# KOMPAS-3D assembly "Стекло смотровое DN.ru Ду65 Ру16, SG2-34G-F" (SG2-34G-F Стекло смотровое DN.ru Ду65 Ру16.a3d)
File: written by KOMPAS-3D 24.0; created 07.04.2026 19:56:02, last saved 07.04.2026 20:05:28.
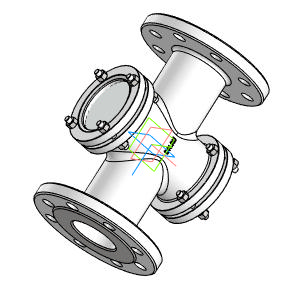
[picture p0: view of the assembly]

Document properties: Автор: Main; Полное имя файла: D:\DN.ru Аутсерс\Стекло смотровое DN.ru\Исходники\Стекло смотровое DN.ru SG2-34G-F тип В ГОСТ 21836-2021 Ду65 Ру16, углеродистая сталь, фланцевое\SG2-34G-F Стекло смотровое DN.ru Ду65 Ру16.a3d

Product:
- Component [detail]: Деталь  | qty 1  | pos. 1  | Масса: 12.292251; Автор: Main; additional columns: Типовые; source file: ДетальДеталь.m3d
- Component [detail]: Стекло  | qty 2  | pos. 2  | Масса: 0.331901; Автор: Main; source file: СтеклоСтекло.m3d
- Component [detail]: ANSI B18.2.4.2M - M8x1,25 - 13  | designation ANSI B18.2.4.2M - M8x1,25  | qty 16  | pos. 3  | Масса: 0.006562; Комментарий: Типы метрических   шестигранных гаек   2; Автор: Main; additional columns: Сталь, мягкая; source file: ANSI B18.2.4.2M - M8x1,25ANSI B18.2.4.2M - M8x1,25 - 13.m3d
- Part/product: Стекло смотровое DN.ru Ду65 Ру16  | designation SG2-34G-F
    Масса: 14
    Раздел спецификации: Прочие изделия
    Примечание: D500-00085

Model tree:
1. Массив по концентрической сетке:1  (labels: Грань.Твердое тело1; Ребро.Твердое тело1; Грань.Solid1; Вершина.Solid1)  (4 pattern instances)
     Шаг 2 = 360; Ориентация = 2

Expressions: SG2-34G-F
Referenced files in D:\DN.ru Аутсерс\Стекло смотровое DN.ru\Исходники\Стекло смотровое DN.ru SG2-34G-F тип В ГОСТ 21836-2021 Ду65 Ру16, углеродистая сталь, фланцевое\: ДетальДеталь.m3d, СтеклоСтекло.m3d, ANSI B18.2.4.2M - M8x1,25ANSI B18.2.4.2M - M8x1,25 - 13.m3d
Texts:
  Стекло Стекло (1)
  Стекло Стекло (2)
  ANSI B18.2.4.2M - M8x1,25 ANSI B18.2.4.2M - M8x1,25 - 13 (1)
  ANSI B18.2.4.2M - M8x1,25 ANSI B18.2.4.2M - M8x1,25 - 13 (2)
  ANSI B18.2.4.2M - M8x1,25 ANSI B18.2.4.2M - M8x1,25 - 13 (3)
  ANSI B18.2.4.2M - M8x1,25 ANSI B18.2.4.2M - M8x1,25 - 13 (4)
  ANSI B18.2.4.2M - M8x1,25 ANSI B18.2.4.2M - M8x1,25 - 13 (5)
  ANSI B18.2.4.2M - M8x1,25 ANSI B18.2.4.2M - M8x1,25 - 13 (6)
  ANSI B18.2.4.2M - M8x1,25 ANSI B18.2.4.2M - M8x1,25 - 13 (7)
  ANSI B18.2.4.2M - M8x1,25 ANSI B18.2.4.2M - M8x1,25 - 13 (8)
  ANSI B18.2.4.2M - M8x1,25 ANSI B18.2.4.2M - M8x1,25 - 13 (9)
  ANSI B18.2.4.2M - M8x1,25 ANSI B18.2.4.2M - M8x1,25 - 13 (10)
  ANSI B18.2.4.2M - M8x1,25 ANSI B18.2.4.2M - M8x1,25 - 13 (11)
  ANSI B18.2.4.2M - M8x1,25 ANSI B18.2.4.2M - M8x1,25 - 13 (12)
  ANSI B18.2.4.2M - M8x1,25 ANSI B18.2.4.2M - M8x1,25 - 13 (13)
  ANSI B18.2.4.2M - M8x1,25 ANSI B18.2.4.2M - M8x1,25 - 13 (14)
  ANSI B18.2.4.2M - M8x1,25 ANSI B18.2.4.2M - M8x1,25 - 13 (15)
  ANSI B18.2.4.2M - M8x1,25 ANSI B18.2.4.2M - M8x1,25 - 13 (16)
  Ось Z.Начало координат
  Ось X.Начало координат
  Ребро.Solid1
